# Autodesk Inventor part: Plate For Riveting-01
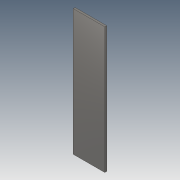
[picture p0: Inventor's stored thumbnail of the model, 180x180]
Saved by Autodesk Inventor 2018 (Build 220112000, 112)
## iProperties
Created: 2018-02
Part Number: Plate For Riveting-01
Material: Steel, Mild
Document SubType Name: Modeling
Designer: STK
Density: 7.85 g/cm^3
Appearance: Semi-Polished
Author: STK
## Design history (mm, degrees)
sketch "Sketch1"
  geometry: L1 (-76.2, -304.8)-(76.2, -304.8); L2 (76.2, -304.8)-(76.2, 304.8); L3 (76.2, 304.8)-(-76.2, 304.8); L4 (-76.2, 304.8)-(-76.2, -304.8); L5 (-76.2, -304.8)-(76.2, 304.8); L6 (76.2, -304.8)-(-76.2, 304.8); 1 further point
  constraints: 12 end point, 2 midpoint, 2 parallel, 1 horizontal, 1 perpendicular
  dimensions: "Width" = 152.4 distance of L3.end L2.end; "Length" = 609.6 distance of L2.end L1.end
extrude "Extrusion1" new body sketch "Sketch1" taper "d3" = 0 deg; distance "Thickness" = 9.525
body "Solid1"
